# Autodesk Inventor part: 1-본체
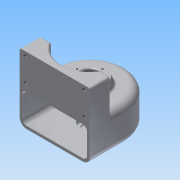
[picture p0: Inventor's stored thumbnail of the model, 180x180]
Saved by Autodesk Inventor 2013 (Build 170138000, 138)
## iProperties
Created: 2015-02
Part Number: 1-본체
Material: 알루미늄 6061
Document SubType Name: Modeling
Designer: Administrator
Density: 2.40731 g/cm^3
Mass: 511.135 g
Surface Area: 707.804 cm^2
Volume: 212.326 cm^3
Author: Administrator
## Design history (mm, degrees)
sketch "스케치1"
  geometry: L1 (-50, 0)-(-50, -50); L2 (50, 0)-(50, -50); L3 (-50, -50)-(50, -50); A1 r 50 centre (0, 0) between (-50, 0) and (50, 0); 1 further point
  constraints: 6 end point, 2 point on circle, 2 tangent, 1 centre point, 1 coincident, 1 parallel, 1 perpendicular, 1 vertical
  dimensions: "d0" = 100 diameter of A1; "d2" = 50 distance from line of L3 point (0, 0)
extrude "돌출1" new body sketch "스케치1" distance "d3" = 50; taper "d4" = 0 deg
feature "쉘1" dims "d5" = 4
sketch "스케치2"
  geometry: L1 (-50, 0)-(-50, -50) reference; L2 (-50, -50)-(50, -50) reference; L3 (50, -50)-(50, 0) reference; L4 (-50, -20)-(-34.641, -20); L5 (50, -20)-(34.641, -20); A1 r 50 centre (0, 0) between (50, 0) and (-50, 0) reference; A2 r 40 centre (0, 0) between (-34.641, -20) and (34.641, -20)
  constraints: 4 end point, 2 collinear, 2 point on circle, 2 point on line, 1 centre point, 1 coincident, 1 perpendicular
  dimensions: "d6" = 80 diameter of A2; "d9" = 30 distance between parallel lines of L2 L4
extrude "돌출2" join sketch "스케치2" distance "d10" = 45; taper "d11" = 0 deg
sketch "스케치3"
  geometry: C1 r 25 at (0, 0); A1 r 40 centre (0, 0) between (-34.641, -20) and (34.641, -20) reference
  constraints: 1 centre point, 1 coincident
  dimensions: "d12" = 50 diameter of C1
extrude "돌출3" join sketch "스케치3" distance "d14" = 10; taper "d15" = -20 deg
sketch "스케치4"
  geometry: C1 r 20 at (0, 0); A1 r 50 centre (0, 0) between (50, 0) and (-50, 0) reference
  constraints: 1 centre point, 1 coincident
  dimensions: "d16" = 40 diameter of C1
extrude "돌출4" join sketch "스케치4" distance "d18" = 9; taper "d19" = 0 deg
hole "구멍1" diameter "d22" = 20; stored, may be unused: countersink angle "d26" = 90 deg, drill point angle "d28" = 118 deg; dims "d23" = 6, "d24" = 28, "d25" = 10, "d27" = 8, "d29" = 10, "d30" = 10
hole "구멍2" diameter "d33" = 20; stored, may be unused: countersink angle "d37" = 90 deg, drill point angle "d39" = 0 deg; dims "d34" = 6, "d35" = 28, "d36" = 8, "d38" = 10, "d40" = 10, "d41" = 10
sketch "스케치5"
  geometry: L1 (0, 95)-(100, 95) reference; L2 (8.25, 89)-(91.75, 89); L3 (91.75, 89)-(91.75, 56); L4 (91.75, 56)-(8.25, 56); L5 (8.25, 56)-(8.25, 89); L6 (0, 50)-(0, 95) reference; 9 further points
  constraints: 8 end point, 4 coincident, 4 midpoint, 2 parallel, 1 horizontal, 1 horizontal alignment, 1 perpendicular, 1 vertical alignment
  dimensions: "d42" = 83.5 distance of L2.start L2.end; "d44" = 33 distance of L4.end L2.start
hole "구멍3" sketch "스케치5" at (8.25, 89), (8.25, 56), (91.75, 56), (91.75, 89) diameter "d45" = 5.134; stored, may be unused: countersink angle "d49" = 90 deg, drill point angle "d51" = 118 deg; dims "d46" = 10, "d47" = 28, "d48" = 8, "d50" = 13
sketch "스케치6"
  geometry: C1 r 14 at (0, 0) reference; C2 r 21.36 at (0, 0) reference; A1 r 18 centre (0, 0) between (0, 18) and (0, -18); 2 further points
  constraints: 4 point on circle, 2 horizontal alignment, 2 vertical alignment, 1 centre point, 1 coincident
  dimensions: "d52" = 36 diameter of A1
hole "구멍4" sketch "스케치6" at (0, 18), (0, -18), (18, 0), (-18, 0) diameter "d54" = 2.459; stored, may be unused: countersink angle "d58" = 90 deg, drill point angle "d60" = 118 deg; dims "d55" = 6, "d56" = 28, "d57" = 8, "d59" = 9
node "작업 평면1"
sketch "스케치7"
  geometry: L1 (50, 50)-(-50, 50) reference; L2 (50, 0)-(-50, 0) reference; 3 further points
  constraints: 1 midpoint, 1 vertical alignment, 1 other
  dimensions: "d61" = 25 distance from line of L2 point (0, 25)
feature "엠보싱1" sketch "스케치7" dims "d0" = 100, "d2" = 50, "d62" = 0.5, "d63" = 0
fillet "모깎기1" dims "d64" = 0.3, "d65" = 10, "d66" = 6
fillet "모깎기2" dims "d67" = 3
fillet "모깎기3" dims "d68" = 3
chamfer "모따기1" distance "d69" = 1; stored, may be unused: second distance "d70" = 2, angle "d71" = 45 deg
node "솔리드1"
